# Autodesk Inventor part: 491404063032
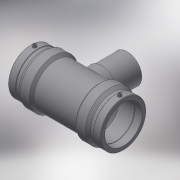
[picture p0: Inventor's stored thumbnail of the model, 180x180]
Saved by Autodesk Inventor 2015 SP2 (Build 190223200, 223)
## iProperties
Created: 2017-06
Part Number: 491404063032
Material: Generic
Description: PLASSON REDUCING TEE 63x32x63
Document SubType Name: Modeling
Designer: KIM
Mass: 356.39 g
Surface Area: 911.298 cm^2
Volume: 356.39 cm^3
Density: 1 g/cm^3
Appearance: Default
Author: KIM
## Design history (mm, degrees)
derived "491404.ipt"
feature "Solid1::491404.ipt"
tag "TaggingFeature1"
body "Solid1"
other parameters: "d0" = 167, "d1" = 63, "d2" = 82, "d3" = 58, "d4" = 33.4, "d5" = 73.8, "d6" = 59.85, "d7" = 63, "d8" = 168 deg, "d10" = 23.2, "d11" = 7.73333, "d13" = 167, "d14" = 17.6296, "d17" = 56.7, "d18" = 63, "d19" = 3.52592, "d20" = 168 deg, "d22" = 76.26, "d23" = 82, "d25" = 135 deg, "d26" = 116.9, "d29" = 58, "d30" = 15, "d31" = 66.8, "d34" = 5 deg, "d35" = 15, "d39" = 5 deg, "d41" = 4, "d42" = 14, "d43" = 0, "d45" = 4, "d46" = 6, "d47" = 0, "d48" = -93, "d49" = 32, "d51" = 0, "d52" = 25.6, "d54" = 0, "d55" = 73.8, "d56" = 82, "d57" = 58.45, "d58" = 135 deg, "d59" = 58, "d60" = 58, "d61" = 135 deg, "d62" = 93, "d72" = 75.985, "d73" = 37.9925, "d74" = -93, "d75" = 33.6, "d77" = 0, "d78" = 25.6, "d80" = 0, "d81" = 32, "d82" = 52, "d83" = 0, "d84" = 3, "d85" = 0, "d86" = 19.33333, "d87" = 74.7348, "d88" = 7.73333, "d89" = 3, "d90" = 0, "d_" = 63, "L_" = 167, "L_1" = 58, "D_" = 82, "A_" = 58, "d_2" = 12, "H_" = 93, "d_1" = 32
